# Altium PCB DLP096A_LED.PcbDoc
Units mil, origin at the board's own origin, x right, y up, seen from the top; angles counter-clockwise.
Board outline 403.54 x 787.4 mil, 2 copper layers (Top Layer, Bottom Layer), stack 62 mil thick; 10 components, 5 nets, 14 pads, 0 vias.
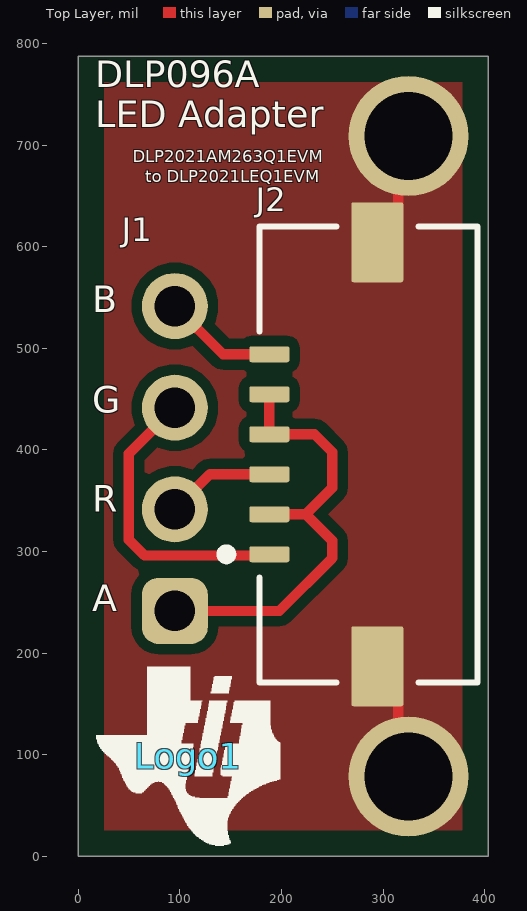
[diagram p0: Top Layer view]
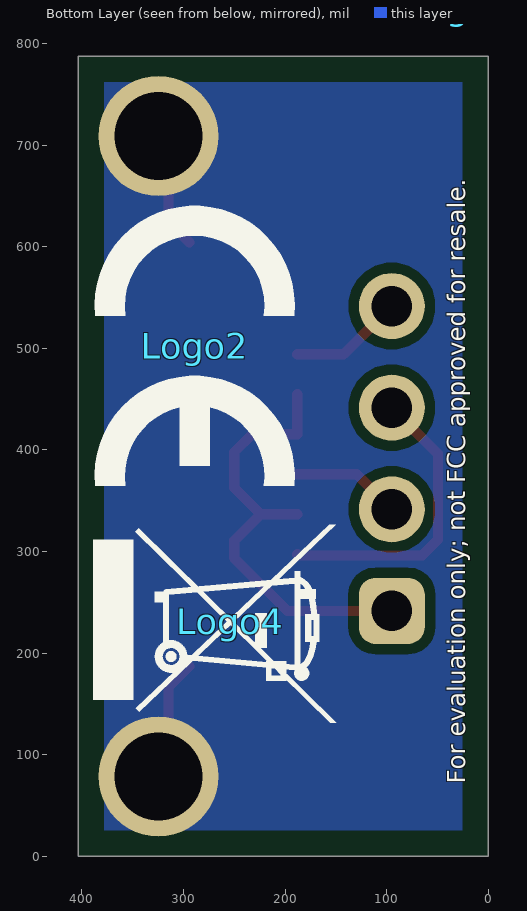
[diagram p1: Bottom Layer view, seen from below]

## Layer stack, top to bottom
Top Solder: solder mask 0.4, Solder Resist, Dk 3.5
Top Layer: signal copper 1.4
Dielectric1: core 59.2, FR-4 High Tg, Dk 4.8
Bottom Layer: signal copper 1.4
Bottom Solder: solder mask 0.4, Solder Resist, Dk 3.5

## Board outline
0,0 403.54,0 403.54,787.4 0,787.4

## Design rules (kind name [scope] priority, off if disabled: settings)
AcuteAngle [All] p1: minimum=4.50000000000000E+0001 checktracksonly=FALSE
AssemblyTestPointUsage [All] p1: valid=2
BoardOutlineClearance BoardOutlineClearance_MountingHoles [OnCopper and InComponentClass('Mounting Holes')] p1: gap=39.37 ignorepadtopadclearanceinfootprint=FALSE
BoardOutlineClearance BoardOutlineClearance_Poly [OnCopper and IsPoly] p2: gap=25 ignorepadtopadclearanceinfootprint=FALSE
BoardOutlineClearance [OnCopper and Not InComponentClass('Logo') and not InComponentClass('FiducialMark') and not InRegion(1000,500,4000,800) and not InPoly] p3: gap=40 ignorepadtopadclearanceinfootprint=FALSE
Clearance Clearance_Keepouts [((IsTrack Or IsArc) And Not InPoly) And IsFree and IsKeepOut vs ((IsTrack Or IsArc) And Not InPoly) And IsFree and IsKeepOut] p1: gap=0 ignorepadtopadclearanceinfootprint=FALSE
Clearance Clearance_Poly [InPolygon] p2: gap=10 ignorepadtopadclearanceinfootprint=TRUE
Clearance Clearance_FiducialMark [IsKeepOut and InComponentClass('FiducialMark') vs IsPad and InComponentClass('FiducialMark')] p3: gap=0 ignorepadtopadclearanceinfootprint=FALSE
Clearance [All] p4: gap=7.87 ignorepadtopadclearanceinfootprint=TRUE
ComponentClearance ComponentClearance_MountingHoles_FiducialMarks [InComponentClass('Mounting Holes') vs InComponentClass('FiducialMark')] p1: gap=50 collisioncheckmode=3 verticalgap=10 showdistances=FALSE
ComponentClearance ComponentClearance_Shunt [InComponentClass('Header') vs InComponentClass('Shunt')] p2: gap=0 collisioncheckmode=3 verticalgap=0 showdistances=FALSE
ComponentClearance ComponentClearance_Logo [InComponentClass('Logo')] p3: gap=30 collisioncheckmode=3 verticalgap=10 showdistances=FALSE
ComponentClearance ComponentClearance_ScrewToNut [(HasFootprint('NY PMS 440 0025 PH')) vs (HasFootprint('Keystone_1902C'))] p4: gap=5 collisioncheckmode=3 verticalgap=10 showdistances=FALSE
ComponentClearance ComponentClearance_MountingHoles [InComponentClass('Mounting Holes')] p5: gap=100 collisioncheckmode=3 verticalgap=100000 showdistances=FALSE
ComponentClearance ComponentClearance_SmallPassives [HasFootprint('0201*') or HasFootprint('0402*') or HasFootprint('0508') or HasFootprint('0603*') or HasFootprint('0612') or HasFootprint('0805*') or HasFootprint('0815*') or HasFootprint('0830*') or HasFootprint('1206*') or HasFootprint('1210*') or HasFootprint('1808*') or HasFootprint('1812*') or HasFootprint('1825*') or HasFootprint('2010*') or HasFootprint('2220*') or HasFootprint('2225*') or HasFootprint('2512*') or HasFootprint('2728*') or HasFootprint('3518*') vs HasFootprint('0201*') or HasFootprint('0402*') or HasFootprint('0508') or HasFootprint('0603*') or HasFootprint('0612') or HasFootprint('0805*') or HasFootprint('0815*') or HasFootprint('0830*') or HasFootprint('1206*') or HasFootprint('1210*') or HasFootprint('1808*') or HasFootprint('1812*') or HasFootprint('1825*') or HasFootprint('2010*') or HasFootprint('2220*') or HasFootprint('2225*') or HasFootprint('2512*') or HasFootprint('2728*') or HasFootprint('3518*')] p6: gap=14.96 collisioncheckmode=3 verticalgap=10 showdistances=FALSE
ComponentClearance ComponentClearance_THtoSMT [IsThruComponent vs IsSMTComponent] p7: gap=30 collisioncheckmode=3 verticalgap=30 showdistances=FALSE
ComponentClearance ComponentClearance_THtoTH [IsThruComponent vs IsThruComponent] p8: gap=20 collisioncheckmode=3 verticalgap=30 showdistances=FALSE
ComponentClearance [All] p9: gap=20 collisioncheckmode=3 verticalgap=10 showdistances=FALSE
DiffPairsRouting [All] p1: maxlimit=100 minlimit=10 mostfreqgap=10 toplayer_minwidth=15 toplayer_maxwidth=15 toplayer_prefwidth=15 bottomlayer_minwidth=15 bottomlayer_maxwidth=15 bottomlayer_prefwidth=15 maxuncoupledlength=1000
FabricationTestPointUsage TestPointUsage [All] p1: valid=2 allowmultiple=FALSE
FabricationTestpoint Testpoint [All] p1: side=3 testpointundercomponent=TRUE minsize=40 maxsize=100 preferedsize=60 minholesize=0 maxholesize=40 preferedholesize=32 testpointgrid=1 allowsidetop=TRUE allowsidebottom=TRUE usegrid=TRUE gridtolerance=0.01
FanoutControl Fanout_LCC [IsLCC] p1: bgadir=Out bgaviamode=Centered fanoutstyle=Auto fanoutdirection=Alternating viagrid=1 // Fanout_LCC (Default Rule)
FanoutControl Fanout_BGA [IsBGA] p2: bgadir=Out bgaviamode=Centered fanoutstyle=Auto fanoutdirection=Alternating viagrid=1 // Fanout_BGA (Default Rule)
FanoutControl Fanout_Default [All] p4: bgadir=Out bgaviamode=Centered fanoutstyle=Auto fanoutdirection=Alternating viagrid=1 // Fanout_Default (Default Rule)
FanoutControl Fanout_Small [(CompPinCount < 5)] p5: bgadir=Out bgaviamode=Centered fanoutstyle=Auto fanoutdirection=OutThenIn viagrid=1 // Fanout_Small (Default Rule)
HoleSize [All] p1: absolutevalues=TRUE maxlimit=251 minlimit=7.87 maxpercent=80.000 minpercent=20.000
MinimumAnnularRing MinimumAnnularRing_ThermalPadVias [IsVia and InAnyComponent] p1: minimumring=5.91
MinimumAnnularRing [All] p2: minimumring=7.87
MinimumSolderMaskSliver MinimumSolderMaskSliver_Logo [InComponentClass('Logo') vs InComponentClass('Logo')] p1: minsoldermaskwidth=0.7
MinimumSolderMaskSliver [All] p2: minsoldermaskwidth=3.94
PlaneConnect [All] p1: planeconnectstyle=Relief reliefexpansion=10 reliefentries=4 reliefconductorwidth=10 reliefairgap=10
PolygonConnect PolygonConnect_4 [All vs IsNamedPolygon('BTM_GND')] p1: thpad.connectstyle=Direct thpad.reliefconductorwidth=10 thpad.reliefentries=4 thpad.polygonreliefangle="90 Angle" thpad.airgapwidth=10 smdpad.connectstyle=Direct smdpad.reliefconductorwidth=10 smdpad.reliefentries=4 smdpad.polygonreliefangle="90 Angle" smdpad.airgapwidth=10 via.connectstyle=Relief via.reliefconductorwidth=10 via.reliefentries=4 via.polygonreliefangle="90 Angle" via.airgapwidth=10
PolygonConnect PolygonConnect_3 [All vs IsNamedPolygon('TOP_GND')] p2: thpad.connectstyle=Direct thpad.reliefconductorwidth=10 thpad.reliefentries=4 thpad.polygonreliefangle="90 Angle" thpad.airgapwidth=10 smdpad.connectstyle=Direct smdpad.reliefconductorwidth=10 smdpad.reliefentries=4 smdpad.polygonreliefangle="90 Angle" smdpad.airgapwidth=10 via.connectstyle=Relief via.reliefconductorwidth=10 via.reliefentries=4 via.polygonreliefangle="90 Angle" via.airgapwidth=10
PolygonConnect PolygonConnect_2 [All vs IsNamedPolygon('BTM_GND')] p3: connectstyle=Relief reliefconductorwidth=10 reliefentries=4 polygonreliefangle="90 Angle" airgapwidth=10
PolygonConnect PolygonConnect_1 [All vs IsNamedPolygon('TOP_GND')] p4: thpad.connectstyle=Direct thpad.reliefconductorwidth=10 thpad.reliefentries=4 thpad.polygonreliefangle="90 Angle" thpad.airgapwidth=10 smdpad.connectstyle=Direct smdpad.reliefconductorwidth=10 smdpad.reliefentries=4 smdpad.polygonreliefangle="90 Angle" smdpad.airgapwidth=10 via.connectstyle=Relief via.reliefconductorwidth=10 via.reliefentries=4 via.polygonreliefangle="90 Angle" via.airgapwidth=10
PolygonConnect [All] p5: connectstyle=Relief reliefconductorwidth=10 reliefentries=4 polygonreliefangle="90 Angle" airgapwidth=10
RoutingVias ThermalPadVias [IsVia and InAnyComponent] p1: holewidth=7.87 width=19.68 viastyle="Through Hole" minholewidth=7.87 minwidth=19.68 maxholewidth=12.99 maxwidth=23.62
RoutingVias [All] p2: holewidth=16 width=34 viastyle="Through Hole" minholewidth=7.87 minwidth=24 maxholewidth=40 maxwidth=65
SilkToBoardRegionClearance [Not ((IsComment or IsDesignator) And (Hide <> 'False')) and not InRegion(1000,500,4000,800)] p1:
SilkToSilkClearance SilkToSilkClearance_Pb-FreeLogo [(HasFootprint('Pb-Free_Overlay_Medium') OR HasFootprint('Pb-Free_Overlay_Small')) vs (HasFootprint('Pb-Free_Overlay_Medium') OR HasFootprint('Pb-Free_Overlay_Small'))] p1: silktosilkclearance=0
SilkToSilkClearance [All] p2: silktosilkclearance=3.94
SilkToSolderMaskClearance SilkToComponentPadClearance [(IsPad or IsFill or IsRegion) and InAnycomponent] p1: minsilkscreentomaskgap=5 clearancetoexposedcopper=TRUE
SilkToSolderMaskClearance "Silk to Solder Mask Opening" [All] p2: minsilkscreentomaskgap=3.94 clearancetoexposedcopper=FALSE
SolderMaskExpansion [All] p1: expansion=1.97 istentingtop=FALSE
UnRoutedNet [All] p1: checkbadconnections=TRUE
Width [All] p1: maxlimit=100 minlimit=6 preferedwidth=10 checkconnectedcopper=TRUE
14 further rules are at their usual default settings.

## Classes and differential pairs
component class Header: J1
component class DLP096A_LED_BlankSheet: J1 J2
component class Logo: Logo1
component class DLP096A_LED_Hardware: Logo1 Logo2 Logo3 Logo4 ZZ1 ZZ2 ZZ3 ZZ4
component class AssemblyNote: ZZ1 ZZ2 ZZ3 ZZ4

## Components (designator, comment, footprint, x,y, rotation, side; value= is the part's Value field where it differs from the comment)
J1 "TSW-104-07-G-S" TSW-104-07-G-S 95,391.56 r90 top
J2 "2005280060" FP-2005280060_CONN_11MM2_5MM25-MFG 285.43,395.73 r90 top
Logo1 "Texas Instruments" TI_Symbol_Overlay_Small 108.27,98.43 r0 top
Logo2 "CE Mark" CE_Mark_5mm 289.04,502.54 r270 bottom
Logo3 "FCC disclaimer" FCC_disclaimer 28.42,836.61 r90 bottom
Logo4 "WEEE logo" WEEE_Minimum 253.87,230.74 r270 bottom
ZZ1 "This Assembly Note is for PCB labels only" AssemblyNoteLabel 147.57,1182.09 r0 top
ZZ2 "These assemblies are ESD sensitive, ESD precautions shall be observed." AssemblyNote 147.57,1073.21 r0 top
ZZ3 "These assemblies must be clean and free from flux and all contaminants. Use of no clean flux is not acceptable." AssemblyNote 147.57,984.65 r0 top
ZZ4 "These assemblies must comply with workmanship standards IPC-A-610 Class 2, unless otherwise specified." AssemblyNote 147.57,896.09 r0 top

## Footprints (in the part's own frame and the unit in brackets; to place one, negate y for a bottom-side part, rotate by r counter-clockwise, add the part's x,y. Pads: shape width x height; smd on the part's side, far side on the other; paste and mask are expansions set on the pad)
AssemblyNote [mil] "Assembly Note"
AssemblyNoteLabel [mil] "Assembly Note for PCB Labels"
CE_Mark_5mm [mil] "Minimum text height for CE Mark"
  silkscreen extent -138,-98 138,98
FCC_disclaimer [mil]
FP-2005280060_CONN_11MM2_5MM25-MFG [mm]
  rrect25% 0.4x1 smd paste+0 mask+0: 1(-2.5,2.475) 2(-1.5,2.475) 3(-0.5,2.475) 4(0.5,2.475) 5(1.5,2.475) 6(2.5,2.475)
  rrect8% 2x1.3 smd paste+0 mask+0: 7(-5.3,-0.225) 8(5.3,-0.225)
  silkscreen extent -5.7,-2.73 5.7,3.67, body extent -6.4,-2.83 6.4,3.08, height 0.25
TI_Symbol_Overlay_Small [mil]
  silkscreen extent -90,-88 91,88
TSW-104-07-G-S [mm] "Samtec 100mil, 1x4, 230 mil above insulator"
  rrect50% 1.65x1.65 hole 1.016: 1(-3.81,0)
  round 1.65 hole 1.016: 2(-1.27,0) 3(1.27,0) 4(3.81,0)
  body extent -5.08,-1.27 5.08,1.27, height 8.38
WEEE_Minimum [mil] "WEEElie bin"
  silkscreen extent -95,-135 99,104

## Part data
J1: library part CMP-0075409-2, "Header, 100mil, 4x1, Gold, TH", Color=Black, Current_A=6.3A, Manufacturer=Samtec, Supplier Part Number 1=SAM1029-04-ND, Voltage_V=550V
J2: library part CMP-0090189-1, "6 Position FFC, FPC Connector Contacts, Bottom 0.039\" (1.00mm) Surface Mount, Right Angle from Molex", Current_A=1A, Digikey Part Number=WM24188CT-ND, Manufacturer=Molex, Mouser Part Number=538-200528-0060, Operating Temperature Range="-40°C to +105°C", Voltage_V=125V
Logo1: library part CMP-0074838-1, "Texas Instrument Corporate Signature"
Logo2: library part CMP-0074844-1
Logo3: library part CMP-0074847-1, "FCC_disclaimer"
Logo4: library part CMP-0074769-1
ZZ1: library part CMP-0003616-3
ZZ2: library part CMP-0077236-1
ZZ3: library part CMP-0077237-1
ZZ4: library part CMP-0077238-1

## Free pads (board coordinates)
  round 118.11 hole 86.61: 105(324.8,78.58) 105(324.8,708.88)

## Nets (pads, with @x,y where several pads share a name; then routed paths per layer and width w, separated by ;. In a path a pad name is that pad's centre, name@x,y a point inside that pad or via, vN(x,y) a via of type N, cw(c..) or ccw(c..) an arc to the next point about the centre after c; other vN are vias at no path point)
BLUE_CATH: J1.4 J2.6 | length 112.6
  Top Layer w10: J1.4 142.4,494.15 J2.6
GND: J2.7 J2.8 pad.105 | length 238.3
  Top Layer w10: J2.7 314.88,166.47 314.88,88.5 pad.105@324.8,78.58 ; J2.8 314.88,624.98 314.88,698.96 pad.105@324.8,708.88
GREEN_CATH: J1.3 J2.1 | length 293.9
  Top Layer w10: J1.3 49.65,396.2 49.65,311.56 65,296.2 186.89,296.2 J2.1
LED_ANODE: J1.1 J2.2 J2.4 J2.5 | length 447.1
  Top Layer w10: J1.1 198.02,241.56 250,293.54 250,310.6 223.93,336.67 ; J2.2 223.93,336.67 ; J2.5 J2.4 232.51,415.41 250,397.92 250,362.74 223.93,336.67
RED_WHITE_CATH: J1.2 J2.3 | length 107.3
  Top Layer w10: J1.2 129.48,376.04 J2.3

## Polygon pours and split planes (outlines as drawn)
GND on Top Layer "TOP_GND" (solid, remove dead copper, pour order 0): 0,0 403.54,0 403.54,787.4 0,787.4
GND on Bottom Layer "BTM_GND" (solid, remove dead copper, pour order 1): 0,0 403.54,0 403.54,787.4 0,787.4

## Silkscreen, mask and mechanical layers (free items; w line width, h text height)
Top Overlay:
  text "DLP096A" at 16.83,748.03 h45
  text "LED Adapter" at 16.83,708.88 h45
  text "DLP2021AM263Q1EVM" at 53.5,679.13 h20
  text "to DLP2021LEQ1EVM" at 65.86,659.45 h20
  text "B" at 13.58,526.45 h45
  text "G" at 13.58,427.83 h45
  text "R" at 13.58,330.21 h45
  text "A" at 13.58,232.59 h45
M1 Board Outline:
  the board outline again, w10
M2 Board Dimensions:
  rectangle: 0,-275 125,-150
  rectangle: 125,-400 500,-275
  lines w7: 0,-275 1000,-275 ; 125,-400 125,-150 ; 250,-400 250,-150 ; 500,-400 500,-150 ; 750,-400 750,-150 ; 0,-400 1000,-400 1000,-150 0,-150 0,-400
M5 Assembly Top:
  lines w10: -292,-930.17 6308,-930.17 ; -292,-726.83 6310,-726.83 ; -292,-523.5 -292,-1133.5 3713,-1133.5 6310,-1133.5 6310,-523.5 -291.5,-523.5 -291.5,-1133.5 1284,-1133.5 ; 2173,-1133.5 2173,-523.5 ; 3440,-726.83 3440,-523.5 ; 4280,-726.83 4280,-523.5 ; 4902,-1140 4902,-937.17
  text "COMPONENTS MARKED 'DNP' SHOULD NOT BE POPULATED." at 1153.5,-318.5 h60
  text "ASSEMBLY VARIANT:" at 1153,-434 h60
  text ".VariantName" at 2189,-434 h60
  text "PCB VIEWED FROM TOP SIDE" at -228.5,-655.67 h60
  text "BOARD #:" at 2248,-655.67 h60
  text ".PRJ_Number" at 2793.5,-655.67 h60
  text "REV:" at 3638,-655.67 h60
  text ".PCB_Rev" at 3929.5,-655.67 h60
  text "SVN REV:" at 4476,-655.67 h60
  text ".VersionControl_RevNumber" at 4982,-655.67 h60
  text "TID #:" at 2248,-859 h60
  text ".TID" at 2793.5,-859 h60
  text "PLOT NAME =" at -228.5,-1064.34 h60
  text ".plot_File_Name" at 577,-1064.34 h60
  text "GENERATED    :" at 2250,-1064.34 h60
  text ".Print_Date" at 3119.5,-1064.34 h60
  text ".Print_Time" at 3848.5,-1064.34 h60
  text "TEXAS INSTRUMENTS" at 5113,-1064.34 h60
M6 Assembly Bottom:
  lines w10: -292.5,-727.33 6309.5,-727.33 ; -290.5,-930.67 6309.5,-930.67 ; 1115.5,-1140.5 1115.5,-937.67 ; 1737.5,-727.33 1737.5,-524 ; 2577.5,-727.33 2577.5,-524 ; 3844.5,-1134 3844.5,-524 ; 4733.5,-1134 6309,-1134 6309,-524 -292.5,-524 -292.5,-1134 2304.5,-1134 6309.5,-1134 6309.5,-524
  text "COMPONENTS MARKED 'DNP' SHOULD NOT BE POPULATED." at 6102,-318 h60
  text ".VariantName" at 5058,-434 h60
  text "ASSEMBLY VARIANT:" at 6097,-434 h60
  text ".VersionControl_RevNumber" at 1035.5,-656.17 h60
  text "SVN REV:" at 1541.5,-656.17 h60
  text ".PCB_Rev" at 2088,-656.17 h60
  text "REV:" at 2379.5,-656.17 h60
  text ".PRJ_Number" at 3224,-656.17 h60
  text "BOARD #:" at 3769.5,-656.17 h60
  text "PCB VIEWED FROM BOTTOM SIDE" at 6246,-656.17 h60
  text ".TID" at 3224,-859.5 h60
  text "TID #:" at 3769.5,-859.5 h60
  text "TEXAS INSTRUMENTS" at 904.5,-1064.84 h60
  text ".Print_Time" at 2169,-1064.84 h60
  text ".Print_Date" at 2898,-1064.84 h60
  text "GENERATED    :" at 3767.5,-1064.84 h60
  text ".plot_File_Name" at 5440.5,-1064.84 h60
  text "PLOT NAME =" at 6246,-1064.84 h60
M9 Title Sheet:
  drawing of 57 lines, arcs and shapes, not listed
  text "1" at 739.84,8036.5 h70
  text "2" at 3235.5,8036.5 h70
  text "3" at 5724.84,8036.5 h70
  text "4" at 8231.51,8036.5 h70
  text "5" at 10730.5,8036.5 h70
  text "6" at 13235.5,8036.5 h70
  text "A" at -416.5,6893.5 h70
  text "A" at 14383.5,6893.5 h70
  text "B" at -416.5,4513.5 h70
  text "B" at 14383.5,4513.5 h70
  text "C" at -416.5,2138.5 h70
  text "C" at 14383.5,2138.5 h70
  text "PROJECT TITLE:" at 11343.5,277.5 h45
  text ".PRJ_Title" at 11393.5,144.17 h70
  text "DESIGNED FOR:" at 11343.5,-23.5 h45
  text ".PRJ_Customer" at 11393.5,-163.5 h70
  text "D" at -416.5,-231.5 h70
  text "D" at 14383.5,-231.5 h70
  text "FILE NAME:" at 11343.5,-323.5 h45
  text ".PCB_File_Name_No_Path" at 11393.5,-443.5 h70
  text "Texas Instruments (TI) and/or its licensors do not warrant the accuracy or completeness of this specification" at 6374,-605.34 h45
  text "ENGINEER:" at 11343.5,-613.5 h45
  text "LAYOUT BY:" at 12848.5,-613.5 h45
  text "or any information contained therein. TI and/or its licensors do not warrant that this design will meet" at 6329.01,-718 h45
  text ".PRJ_Engineer" at 11393.5,-768.49 h70
  text ".PCB_Layout" at 12899,-768.49 h70
  text "the specifications, will be suitable for your application or fit for any particular purpose, or will operate in" at 6329.01,-830.67 h45
  text ".Layer_Name" at 577,-858.49 h60
  text "ALTIUM DESIGNER VERSION:" at 12848.5,-923.5 h45
  text "an implementation. TI and/or its licensors do not warrant that the design is production worthy. You should" at 6329.01,-943.33 h45
  text "completely validate and test your design implementation to confirm the system functionality for your application." at 6374,-1056 h45
  text ".print_Scale" at 11393.5,-1056.83 h70
  text ".Application_BuildNumber" at 12899,-1056.83 h70
  text "1" at 739.84,-1263.5 h70
  text "2" at 3235.5,-1263.5 h70
  text "3" at 5724.84,-1263.5 h70
  text "4" at 8231.51,-1263.5 h70
  text "5" at 10730.5,-1263.5 h70
  text "6" at 13235.5,-1263.5 h70
M10 Fab Notes:
  drawing of 189 lines, arcs and shapes, not listed
  text "DESIGN INFORMATION" at 12382.02,6356.17 h60
  text "MIN. TRACK WIDTH:" at 11737.46,6224.05 h60
  text "8" at 12833.7,6224.05 h60
  text "MIL" at 12988.46,6224.05 h60
  text "7.874" at 12667.32,6102.36 h60
  text "MIN. CLEARANCE:" at 11737.46,6099.92 h60
  text "MIL" at 12988.46,6099.92 h60
  text "MIN. VIA PAD SIZE:" at 11737.46,5975.8 h60
  text "24" at 12803.71,5975.8 h60
  text "MIL" at 12988.46,5975.8 h60
  text "0.05mm (2MIL)" at 12432.46,5845.9 h60
  text "MINIMUM ANNULAR RING" at 11408.23,5837.67 h60
  text "EXTERNAL" at 13140.46,5837.67 h60
  text "PER" at 11608.23,5727.55 h60
  text "IPC-D-275 CLASS 2 LEVEL C" at 11828.23,5727.54 h60
  text "MIL, HOLES" at 13316.46,5627.07 h60
  text "+/-" at 12924,5618.48 h60
  text "+/-" at 13778,5618.48 h60
  text "REGISTRATION TOLERANCES:" at 11408.23,5617.42 h60
  text "METAL" at 12608,5617.42 h60
  text "5" at 13184.2,5617.42 h60
  text "3" at 14017.2,5617.42 h60
  text "MIL" at 14133.46,5617.42 h60
  text "HOLE SIZE TOLERANCE (UNLESS OTHERWISE SPECIFIED):" at 11408.23,5519.1 h60
  text "+/-" at 13778,5516.23 h60
  text "3" at 14017.2,5515.17 h60
  text "MIL" at 14133.46,5515.17 h60
  text "MATERIAL:" at 11333.46,5377.52 h60
  text "FR-4 High Tg" at 12319.9,5249 h60
  text "X" at 12175.46,5241.01 h60
  text "FR-4" at 11754.46,5236.49 h60
  text "OTHER" at 13242.46,5236.49 h60
  text "62 MIL (1.6mm) +/-10%" at 12074.56,5093.46 h60
  text "X" at 11954.46,5091.01 h60
  text "THICKNESS:" at 11408.23,5085.24 h60
  text "OTHER" at 13359.46,5085.24 h60
  text "TOLERANCE:" at 11408.23,4946.92 h60
  text "X" at 12256.46,4946.92 h60
  text "ANSI IPC-6012 TYPE 3 CLASS 2" at 12434.48,4946.92 h60
  text "OTHER +/-" at 12434.46,4802.73 h60
  text "BOW & TWIST:" at 11408.23,4657.54 h60
  text "X" at 12256.46,4657.54 h60
  text "ANSI IPC-6012 TYPE 3 CLASS 2" at 12434.48,4657.54 h60
  text "OTHER +/-" at 12434.46,4510.85 h60
  text "DRILLING:" at 11333.46,4380.23 h60
  text "NC_DRILL FILES" at 13094.46,4275.04 h60
  text "REFERENCE:" at 11408.23,4271.1 h60
  text "X" at 12065.46,4271.01 h60
  text "AS SHOWN" at 12243.46,4271.1 h60
  text "X" at 12966.46,4271.1 h60
  text "OTHER" at 13392.46,4128.85 h60
  text "PTH COPPER THICKNESS:" at 11407.91,4125.32 h60
  text "X" at 12547.14,4125.32 h60
  text "20-30 um" at 12675.14,4125.32 h60
  text "BOARD FINISH:" at 11333.46,3977.73 h60
  text "SILKSCREEN:" at 11488.68,3867.6 h60
  text "X" at 12446.46,3867.6 h60
  text "TOP" at 12563.46,3867.6 h60
  text "X" at 12956.46,3867.6 h60
  text "BOTTOM" at 13074.46,3867.6 h60
  text "SILKSCREEN COLOR:" at 11488.68,3712.41 h60
  text "X" at 12445.46,3712.41 h60
  text "WHITE" at 12563.46,3712.41 h60
  text "OTHER" at 13074.46,3712.41 h60
  text "X" at 12576.46,3568.96 h60
  text "GREEN" at 12694.46,3568.96 h60
  text "OTHER" at 13312.46,3568.96 h60
  text "SOLDER RESIST COLOR:" at 11488.68,3562.1 h60
  text "X" at 12576.46,3414.71 h60
  text "MATTE" at 12694.46,3414.71 h60
  text "SEMI-GLOSS" at 13312,3414.07 h60
  text "IMMERSION GOLD (ENIG)" at 12394.46,3241.94 h60
  text "ENEPIG" at 13732,3234.72 h60
  text "SURFACE FINISH:" at 11333.46,3233.72 h60
  text "X" at 12216.46,3233.72 h60
  text "IMM. TIN/SILVER OR EQUIV" at 11663,3096.4 h60
  text "OTHER" at 13094.46,3092.47 h60
  text "ARRAY/PANEL:" at 11333.46,2937.09 h60
  text "CUT AND TRIM PER M1 BOARD OUTLINE" at 12394.46,2928.87 h60
  text "N.C. ROUTE" at 12394.46,2792.9 h60
  text "X" at 13082.46,2792.9 h60
  text "V. SCORE" at 13260.46,2792.9 h60
  text "CERTIFICATION:" at 11333.46,2663.77 h60
  text "MATERIALS AND WORKMANSHIP FOR ALL PCBS" at 12058.46,2663.77 h60
  text "TO MEET OR EXCEED THE REQUIREMENTS OF:" at 12058.46,2569.71 h60
  text "X" at 11695.97,2441.08 h60
  text "ANSI IPC-A-600F CLASS ->" at 11823.96,2441.08 h60
  text "X" at 13471.97,2441.08 h60
  text "2" at 13581.96,2441.08 h60
  text "1" at 13266.96,2439.58 h60
  text "3" at 13935.96,2439.58 h60
  text "X" at 12507.97,2293.39 h60
  text "RoHS" at 12635.96,2293.39 h60
  text "OTHER" at 13280.36,2293.39 h60
  text "PER ORDER" at 13677.42,2293.39 h60
  text "ALL BOARDS MUST MEET OR EXCEED UL94-V0 REQUIREMENTS." at 11361,2139.57 h60
  text "PCB MUST BEAR THE UL94V-0 UL REGISTERED MATERIAL ID NUMBER" at 11361,2023.5 h60
  text "ADDITIONAL REQUIREMENTS:" at 11333.46,1854.08 h60
  text "MICROSECTION:" at 11408.23,1746.95 h60
  text "YES" at 12313.96,1746.95 h60
  text "REQUIRED" at 13175.46,1602.62 h60
  text "BARE BOARD ELEC. TEST:" at 11408.23,1599.76 h60
  text "NONE" at 12713.96,1599.76 h60
  text "X" at 13057.46,1599.76 h60
  text "PER ORDER" at 13767.46,1599.76 h60
  text "XX MIL VIAS REQUIRE NON-CONDUCTIVE FILL AND PLANARIZE" at 11576.38,1394.82 h59
  text "XX MIL VIAS REQUIRE CONDUCTIVE FILL AND PLANARIZE" at 11584.38,1290.84 h60
  text "OUTER XX MIL TRACES REQUIRE 50 OHM SINGLE-ENDED IMPEDANCE" at 11583.39,1127.46 h58
  text "LAYER 2 & 3 (INNER LAYERS) XX MIL WIDE, XX MIL SPACE / TRACES REQUIRE 100 OHM DIFFERENTIAL IMPEDANCE" at 11575.39,891.74 h60
M11 Gerber Information:
  lines w10: -292,-930.17 6308,-930.17 ; -292,-726.83 6310,-726.83 ; -292,-523.5 -292,-1133.5 3713,-1133.5 6310,-1133.5 6310,-523.5 -291.5,-523.5 -291.5,-1133.5 1284,-1133.5 ; 2173,-1133.5 2173,-523.5 ; 3440,-726.83 3440,-523.5 ; 4280,-726.83 4280,-523.5 ; 4902,-1140 4902,-937.17
  text "ALL ARTWORK VIEWED FROM TOP SIDE" at -228.5,-655.67 h60
  text "BOARD #:" at 2248,-655.67 h60
  text ".PRJ_Number" at 2793.5,-655.67 h60
  text "REV:" at 3638,-655.67 h60
  text ".PCB_Rev" at 3929.5,-655.67 h60
  text "SVN REV:" at 4476,-655.67 h60
  text ".VersionControl_RevNumber" at 4982,-655.67 h60
  text "LAYER NAME =" at -228.5,-858.49 h60
  text "TID #:" at 2248,-859 h60
  text ".TID" at 2793.5,-859 h60
  text "PLOT NAME =" at -228.5,-1064.34 h60
  text ".plot_File_Name" at 577,-1064.34 h60
  text "GENERATED    :" at 2250,-1064.34 h60
  text ".Print_Date" at 3119.5,-1064.34 h60
  text ".Print_Time" at 3848.5,-1064.34 h60
  text "TEXAS INSTRUMENTS" at 5113,-1064.34 h60
M12 Stackup:
  drawing of 191 lines, arcs and shapes, not listed
  text "Layer" at 9821.59,7874.94 h60
  text "Name" at 10231.51,7874.94 h60
  text "Material" at 11161.25,7874.94 h60
  text "Thickness" at 12021.02,7874.94 h60
  text "Constant" at 12670.85,7874.94 h60
  text "Board Layer Stack" at 13240.71,7874.94 h60
  text "Top Overlay" at 10231.51,7754.94 h60
  text "Top Solder" at 10231.51,7634.94 h60
  text "Solder Resist" at 11161.25,7634.94 h60
  text "0.40mil" at 12021.02,7634.94 h60
  text "3.5" at 12670.85,7634.94 h60
  text "1" at 9821.59,7514.94 h60
  text "Top Layer" at 10231.51,7514.94 h60
  text "1.40mil" at 12021.02,7514.94 h60
  text "Dielectric1" at 10231.51,7394.94 h60
  text "FR-4 High Tg" at 11161.25,7394.94 h60
  text "59.20mil" at 12021.02,7394.94 h60
  text "4.8" at 12670.85,7394.94 h60
  text "2" at 9821.59,7274.94 h60
  text "Bottom Layer" at 10231.51,7274.94 h60
  text "1.40mil" at 12021.02,7274.94 h60
  text "Bottom Solder" at 10231.51,7154.94 h60
  text "Solder Resist" at 11161.25,7154.94 h60
  text "0.40mil" at 12021.02,7154.94 h60
  text "3.5" at 12670.85,7154.94 h60
  text "Bottom Overlay" at 10231.51,7034.94 h60
Drill Drawing:
  circle w10: c673.1,450.79 r27.6
  lines w10: 645.5,547.39 700.71,547.39 700.71,602.6 645.5,602.6 645.5,547.39
  lines w12: 595.45,385.92 3825.23,385.92 ; 595.45,634.34 3825.23,634.34 ; 933.18,261.71 933.18,758.55 ; 1264.93,261.71 1264.93,758.55 ; 1901.24,261.71 1901.24,758.55 ; 2160.24,261.71 2160.24,758.55 ; 2535.27,261.71 2535.27,758.55 ; 3259.01,261.71 3259.01,758.55 ; 595.45,261.71 3825.23,261.71 3825.23,758.55 595.45,758.55 595.45,261.71
  text "Symbol" at 669.98,671.6 h72
  text "Quantity" at 970.44,671.6 h72
  text "Finished Hole Size" at 1302.19,671.6 h72
  text "Plated" at 1938.5,671.6 h72
  text "Hole Type" at 2197.5,671.6 h72
  text "Drill Layer Pair" at 2572.53,671.6 h72
  text "Hole Tolerance" at 3296.27,671.6 h72
  text "4" at 970.44,547.39 h60
  text "40.00mil (1.016mm)" at 1302.19,547.39 h60
  text "PTH" at 1938.5,547.39 h60
  text "Round" at 2197.5,547.39 h60
  text "Top Layer - Bottom Layer" at 2572.53,547.39 h60
  text "2" at 970.44,423.18 h60
  text "86.61mil (2.200mm)" at 1302.19,423.18 h60
  text "PTH" at 1938.5,423.18 h60
  text "Round" at 2197.5,423.18 h60
  text "Top Layer - Bottom Layer" at 2572.53,423.18 h60
  text "6 Total" at 970.44,298.98 h60
M17 Embedded Cavity:
  text ".Layer_Name" at 577,-858.49 h60
M18 Embedded Assembly:
  text ".Layer_Name" at 577,-858.49 h60
M19 Embedded Keepout:
  text ".Layer_Name" at 577,-858.49 h60

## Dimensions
0,-400 to 1000,-400 on M2 Board Dimensions
0,0 to 0,787.4 on M2 Board Dimensions
0,0 to 403.54,0 on M2 Board Dimensions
